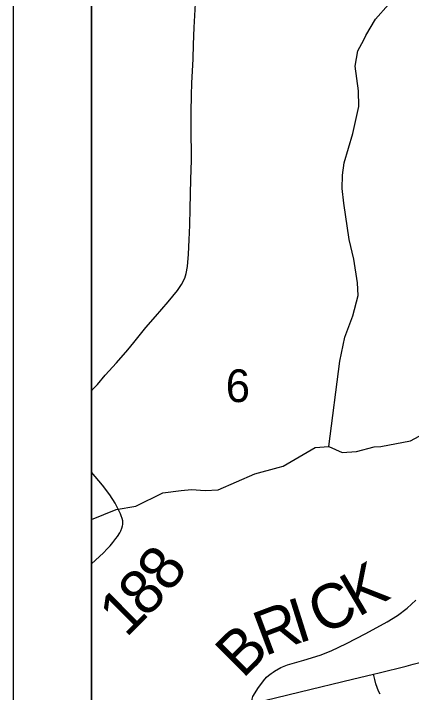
# Model space of a CAD drawing. Extents: x 0 to 34, y 0 to 22.
# Drawn here: x 23.917 to 24.426, y 16.381 to 17.25 of the extents above; entities that cross this region are included whole.
import ezdxf

# ---------------------------------------------------------------- set-up
doc = ezdxf.new("R2010")
doc.units = 0
for name, color, linetype in [('GM_X_Adjacent_County', 7, 'Continuous'), ('GM_X_County', 7, 'Continuous'), ('GM_X_Minor_River', 7, 'Continuous'), ('GM_X_Section', 7, 'Continuous'), ('GM_X_Section_Text', 7, 'Continuous'), ('GM_X_Township', 7, 'Continuous'), ('GM_X_Township_Road', 7, 'Continuous'), ('GM_X_Township_Road_Text', 7, 'Continuous'), ('GM_X_Township_Subdivision', 7, 'Continuous'), ('GM_X_US_Route', 7, 'Continuous'), ('SH_Data', 7, 'Continuous')]:
    doc.layers.add(name, color=color, linetype=linetype)

msp = doc.modelspace()

# ---------------------------------------------------------------- linework, layer by layer
at = {"layer": 'GM_X_Adjacent_County'}
msp.add_lwpolyline([(28.7526, 20.9), (24.01667, 20.9), (24.01667, 14.1), (28.5181, 14.1)], dxfattribs=at)
at = {"layer": 'GM_X_County'}
msp.add_lwpolyline([(28.7526, 20.9), (24.01667, 20.9), (24.01667, 14.1), (28.5181, 14.1)], dxfattribs=at)
at = {"layer": 'GM_X_Minor_River'}
for points in [[(24.32055, 16.69564), (24.3346, 16.80497), (24.34121, 16.83574), (24.35125, 16.86311), (24.35828, 16.88895), (24.35741, 16.90526), (24.35266, 16.93557), (24.34682, 16.96057), (24.33969, 17.00718), (24.33767, 17.02613), (24.33794, 17.0432), (24.3401, 17.05877), (24.35122, 17.09639), (24.35894, 17.13096), (24.35843, 17.15106), (24.35443, 17.18252), (24.35771, 17.20226), (24.36557, 17.21635), (24.36818, 17.22168), (24.38054, 17.24262), (24.39708, 17.26131)], [(24.01667, 16.6022), (24.01668, 16.60223), (24.04803, 16.61496), (24.07338, 16.6193), (24.1081, 16.63659), (24.13119, 16.6394), (24.14481, 16.64063), (24.16224, 16.63922), (24.1789, 16.64009), (24.22572, 16.66088), (24.25559, 16.66866), (24.26202, 16.6706), (24.30314, 16.69439), (24.32055, 16.69564), (24.33765, 16.68816), (24.35619, 16.68942), (24.3785, 16.69525), (24.38721, 16.69569), (24.42503, 16.70276), (24.44202, 16.71198)]]:
    msp.add_lwpolyline(points, dxfattribs=at)
at = {"layer": 'GM_X_Section'}
msp.add_line((24.01667, 17.32351), (24.01667, 16.32239), dxfattribs=at)
at = {"layer": 'GM_X_Township'}
msp.add_lwpolyline([(24.01667, 18.44021), (24.01667, 14.1), (28.5181, 14.1)], dxfattribs=at)
at = {"layer": 'GM_X_Township_Road'}
for points in [[(24.01667, 16.76681), (24.01843, 16.7691), (24.02407, 16.77508), (24.0341, 16.78693), (24.04874, 16.80299), (24.06302, 16.81926), (24.07066, 16.82886), (24.08634, 16.84803), (24.09853, 16.86213), (24.11483, 16.88083), (24.12655, 16.89526), (24.13184, 16.90292), (24.13601, 16.91123), (24.13787, 16.91714), (24.13944, 16.92631), (24.14089, 16.94177), (24.14162, 16.96036), (24.14236, 16.97893), (24.143, 17.0005), (24.14399, 17.03732), (24.14427, 17.04968), (24.14445, 17.06208), (24.14448, 17.0775), (24.14427, 17.08973), (24.14422, 17.09587), (24.14438, 17.12366), (24.1448, 17.14539), (24.14524, 17.16087), (24.14662, 17.19173), (24.14737, 17.21033), (24.1481, 17.23204), (24.151, 17.28641)], [(24.01667, 16.54568), (24.03174, 16.55943), (24.03657, 16.56459), (24.04039, 16.56863), (24.04387, 16.57267), (24.04782, 16.57782), (24.04977, 16.58041), (24.05262, 16.58513), (24.05409, 16.58793), (24.05559, 16.59131), (24.05633, 16.59433), (24.05655, 16.59579), (24.05662, 16.59741), (24.05653, 16.59904), (24.05645, 16.60051), (24.05582, 16.60355), (24.05453, 16.60682), (24.05353, 16.60932), (24.04663, 16.62324), (24.04002, 16.63375), (24.03054, 16.64603), (24.01667, 16.66278)], [(24.24925, 16.40695), (24.25091, 16.4082), (24.25907, 16.41263), (24.26773, 16.41602), (24.28855, 16.42209), (24.3093, 16.42841), (24.32376, 16.43404), (24.34331, 16.44351), (24.36809, 16.45641), (24.3954, 16.47109), (24.40852, 16.4793), (24.42084, 16.48869), (24.43223, 16.49917)], [(24.22255, 16.36689), (24.22248, 16.3723), (24.22266, 16.37393), (24.22318, 16.37549), (24.22389, 16.37696), (24.22956, 16.386), (24.23699, 16.39595), (24.24092, 16.40032), (24.24349, 16.40261), (24.24686, 16.40513), (24.24925, 16.40695)]]:
    msp.add_lwpolyline(points, dxfattribs=at)
at = {"layer": 'GM_X_Township_Subdivision'}
msp.add_lwpolyline([(24.38653, 16.37884), (24.38431, 16.38258), (24.38244, 16.38721), (24.3808, 16.39175), (24.37945, 16.39741), (24.3778, 16.40434)], dxfattribs=at)
at = {"layer": 'GM_X_US_Route'}
for points in [[(24.41959, 16.41469), (24.42867, 16.41694), (24.4613, 16.42503), (24.49205, 16.43178), (24.52899, 16.43879), (24.56109, 16.44338), (24.59048, 16.44661), (24.61753, 16.449), (24.6228, 16.44946), (24.63827, 16.45055), (24.66931, 16.45195), (24.69727, 16.45262), (24.72212, 16.45248), (24.77516, 16.45199), (24.82818, 16.45129), (24.88124, 16.45079), (24.94539, 16.44994), (24.9658, 16.45039)], [(24.22255, 16.36689), (24.28384, 16.38162), (24.351, 16.3978), (24.3778, 16.40434), (24.38525, 16.40616), (24.41959, 16.41469)]]:
    msp.add_lwpolyline(points, dxfattribs=at)
at = {"layer": 'SH_Data'}
for points in [[(23.91667, 21), (30.91667, 21), (30.91667, 14), (23.91667, 14)], [(24.01667, 20.9), (30.81667, 20.9), (30.81667, 14.1), (24.01667, 14.1)]]:
    msp.add_lwpolyline(points, close=True, dxfattribs=at)

# ---------------------------------------------------------------- texts
at = {"layer": 'GM_X_Section_Text'}
msp.add_text('6', height=0.04186, rotation=0.00001, dxfattribs=at).set_placement((24.18848, 16.75256))
at = {"layer": 'GM_X_Township_Road_Text'}
for s, rotation, p in [('8', 53.76018, (24.11655, 16.50686)), ('K', 30.58577, (24.35818, 16.47657)), ('8', 45.17124, (24.08584, 16.47499)), ('C', 26.12177, (24.31203, 16.45373)), ('1', 44.94817, (24.0609, 16.45009)), ('I', 17.56357, (24.28119, 16.44324)), ('R', 20.66705, (24.23829, 16.42704)), ('B', 44.70745, (24.21039, 16.39759))]:
    msp.add_text(s, height=0.05682, rotation=rotation, dxfattribs=at).set_placement(p)

doc.saveas('drawing.dxf')
